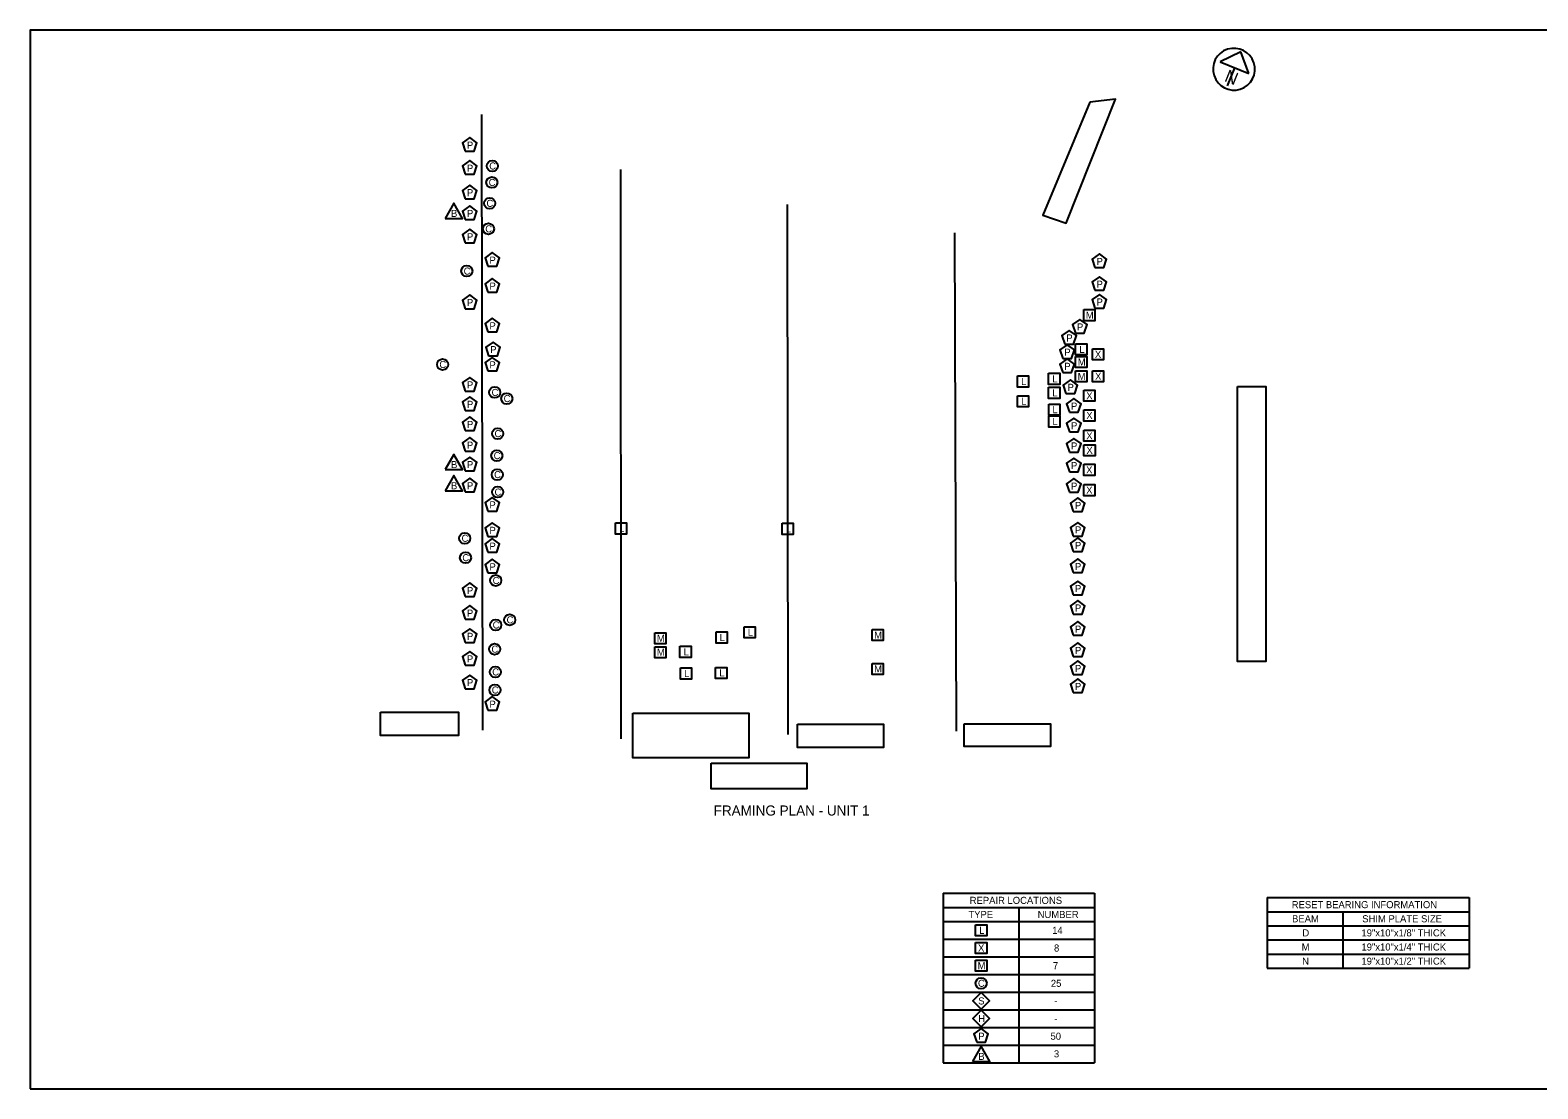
# Model space of a CAD drawing. Extents: x 100 to 161, y 98.7 to 121.
# Drawn here: x 100 to 129.89, y 100 to 121 of the extents above; entities that cross this region are included whole.
import ezdxf

# ---------------------------------------------------------------- set-up
doc = ezdxf.new("R2010")
doc.units = 0
for name, color, linetype in [('BR_P_Gen_Text', 7, 'Continuous'), ('BR_X_Sub_Centerline', 7, 'Continuous'), ('BR_X_Sub_Text', 7, 'Continuous'), ('SC_Scratch1', 7, 'Continuous'), ('SH_Data', 7, 'Continuous'), ('SH_Masking', 7, 'Continuous')]:
    doc.layers.add(name, color=color, linetype=linetype)

msp = doc.modelspace()

# ---------------------------------------------------------------- linework, layer by layer
at = {"layer": 'BR_P_Gen_Text'}
for p, q in [((118.103, 103.879), (118.103, 100.519)), ((118.103, 103.879), (121.103, 103.879)), ((121.103, 103.879), (121.103, 100.519)), ((124.527, 103.794), (124.527, 102.394)), ((124.527, 103.794), (128.527, 103.794)), ((128.527, 103.794), (128.527, 102.394)), ((118.103, 103.599), (121.103, 103.599)), ((119.603, 103.599), (119.603, 100.519)), ((124.527, 103.514), (128.527, 103.514)), ((126.027, 103.514), (126.027, 102.394)), ((118.103, 103.319), (121.103, 103.319)), ((124.527, 103.234), (128.527, 103.234)), ((118.103, 102.969), (121.103, 102.969)), ((124.527, 102.954), (128.527, 102.954)), ((118.103, 102.619), (121.103, 102.619)), ((124.527, 102.674), (128.527, 102.674)), ((118.103, 102.269), (121.103, 102.269)), ((124.527, 102.394), (128.527, 102.394)), ((118.103, 101.919), (121.103, 101.919)), ((118.103, 101.569), (121.103, 101.569)), ((118.103, 101.219), (121.103, 101.219)), ((118.103, 100.869), (121.103, 100.869)), ((118.103, 100.519), (121.103, 100.519))]:
    msp.add_line(p, q, dxfattribs=at)
for points in [[(108.627, 118.598), (108.803, 118.598), (108.858, 118.765), (108.715, 118.869), (108.573, 118.765)], [(108.627, 118.14), (108.803, 118.14), (108.858, 118.308), (108.715, 118.412), (108.573, 118.308)], [(108.627, 117.654), (108.803, 117.654), (108.858, 117.822), (108.715, 117.926), (108.573, 117.822)], [(108.225, 117.265), (108.572, 117.265), (108.398, 117.565)], [(108.627, 117.244), (108.803, 117.244), (108.858, 117.412), (108.715, 117.515), (108.573, 117.412)], [(108.627, 116.781), (108.803, 116.781), (108.858, 116.949), (108.715, 117.052), (108.573, 116.949)], [(109.074, 116.317), (109.25, 116.317), (109.304, 116.485), (109.162, 116.588), (109.019, 116.485)], [(121.109, 116.291), (121.285, 116.291), (121.34, 116.458), (121.197, 116.562), (121.054, 116.458)], [(109.074, 115.802), (109.25, 115.802), (109.304, 115.97), (109.162, 116.074), (109.019, 115.97)], [(121.109, 115.839), (121.285, 115.839), (121.34, 116.006), (121.197, 116.11), (121.054, 116.006)], [(108.627, 115.475), (108.803, 115.475), (108.858, 115.643), (108.715, 115.747), (108.573, 115.643)], [(121.109, 115.487), (121.285, 115.487), (121.34, 115.655), (121.197, 115.758), (121.054, 115.655)], [(120.886, 115.456), (121.106, 115.456), (121.106, 115.236), (120.886, 115.236)], [(109.074, 115.013), (109.25, 115.013), (109.304, 115.181), (109.162, 115.285), (109.019, 115.181)], [(120.721, 114.991), (120.897, 114.991), (120.952, 115.159), (120.809, 115.263), (120.667, 115.159)], [(109.088, 114.541), (109.265, 114.541), (109.319, 114.709), (109.177, 114.813), (109.034, 114.709)], [(120.511, 114.773), (120.687, 114.773), (120.741, 114.94), (120.599, 115.044), (120.456, 114.94)], [(109.074, 114.239), (109.25, 114.239), (109.304, 114.407), (109.162, 114.51), (109.019, 114.407)], [(120.47, 114.49), (120.646, 114.49), (120.701, 114.657), (120.558, 114.761), (120.415, 114.657)], [(120.47, 114.209), (120.646, 114.209), (120.701, 114.377), (120.558, 114.481), (120.415, 114.377)], [(120.727, 114.777), (120.947, 114.777), (120.947, 114.557), (120.727, 114.557)], [(120.727, 114.527), (120.947, 114.527), (120.947, 114.307), (120.727, 114.307)], [(121.059, 114.679), (121.279, 114.679), (121.279, 114.459), (121.059, 114.459)], [(120.191, 114.194), (120.411, 114.194), (120.411, 113.974), (120.191, 113.974)], [(120.727, 114.242), (120.947, 114.242), (120.947, 114.022), (120.727, 114.022)], [(121.062, 114.244), (121.282, 114.244), (121.282, 114.024), (121.062, 114.024)], [(108.627, 113.841), (108.803, 113.841), (108.858, 114.009), (108.715, 114.113), (108.573, 114.009)], [(119.573, 114.14), (119.793, 114.14), (119.793, 113.92), (119.573, 113.92)], [(120.191, 113.915), (120.411, 113.915), (120.411, 113.695), (120.191, 113.695)], [(120.534, 113.794), (120.71, 113.794), (120.765, 113.961), (120.622, 114.065), (120.48, 113.961)], [(108.627, 113.457), (108.803, 113.457), (108.858, 113.625), (108.715, 113.728), (108.573, 113.625)], [(119.573, 113.749), (119.793, 113.749), (119.793, 113.529), (119.573, 113.529)], [(120.603, 113.422), (120.779, 113.422), (120.834, 113.59), (120.691, 113.693), (120.548, 113.59)], [(120.888, 113.858), (121.108, 113.858), (121.108, 113.638), (120.888, 113.638)], [(108.627, 113.059), (108.803, 113.059), (108.858, 113.226), (108.715, 113.33), (108.573, 113.226)], [(120.195, 113.582), (120.415, 113.582), (120.415, 113.362), (120.195, 113.362)], [(120.195, 113.347), (120.415, 113.347), (120.415, 113.127), (120.195, 113.127)], [(120.603, 113.033), (120.779, 113.033), (120.834, 113.201), (120.691, 113.304), (120.548, 113.201)], [(120.888, 113.467), (121.108, 113.467), (121.108, 113.247), (120.888, 113.247)], [(120.888, 113.064), (121.108, 113.064), (121.108, 112.844), (120.888, 112.844)], [(108.627, 112.647), (108.803, 112.647), (108.858, 112.814), (108.715, 112.918), (108.573, 112.814)], [(120.603, 112.63), (120.779, 112.63), (120.834, 112.798), (120.691, 112.902), (120.548, 112.798)], [(120.892, 112.775), (121.112, 112.775), (121.112, 112.555), (120.892, 112.555)], [(108.225, 112.282), (108.572, 112.282), (108.398, 112.582)], [(108.627, 112.26), (108.803, 112.26), (108.858, 112.428), (108.715, 112.532), (108.573, 112.428)], [(120.603, 112.241), (120.779, 112.241), (120.834, 112.409), (120.691, 112.513), (120.548, 112.409)], [(120.886, 112.388), (121.106, 112.388), (121.106, 112.168), (120.886, 112.168)], [(108.225, 111.863), (108.572, 111.863), (108.398, 112.163)], [(108.627, 111.842), (108.803, 111.842), (108.858, 112.009), (108.715, 112.113), (108.573, 112.009)], [(120.603, 111.834), (120.779, 111.834), (120.834, 112.002), (120.691, 112.105), (120.548, 112.002)], [(120.886, 111.985), (121.106, 111.985), (121.106, 111.765), (120.886, 111.765)], [(109.074, 111.462), (109.25, 111.462), (109.304, 111.629), (109.162, 111.733), (109.019, 111.629)], [(120.681, 111.451), (120.857, 111.451), (120.911, 111.619), (120.769, 111.723), (120.626, 111.619)], [(109.074, 110.957), (109.25, 110.957), (109.304, 111.125), (109.162, 111.228), (109.019, 111.125)], [(111.605, 111.224), (111.825, 111.224), (111.825, 111.004), (111.605, 111.004)], [(114.909, 111.219), (115.129, 111.219), (115.129, 110.999), (114.909, 110.999)], [(120.681, 110.965), (120.857, 110.965), (120.911, 111.133), (120.769, 111.237), (120.626, 111.133)], [(109.074, 110.643), (109.25, 110.643), (109.304, 110.811), (109.162, 110.915), (109.019, 110.811)], [(120.681, 110.657), (120.857, 110.657), (120.911, 110.825), (120.769, 110.929), (120.626, 110.825)], [(109.074, 110.235), (109.25, 110.235), (109.304, 110.402), (109.162, 110.506), (109.019, 110.402)], [(120.681, 110.239), (120.857, 110.239), (120.911, 110.407), (120.769, 110.51), (120.626, 110.407)], [(108.627, 109.763), (108.803, 109.763), (108.858, 109.931), (108.715, 110.034), (108.573, 109.931)], [(120.681, 109.802), (120.857, 109.802), (120.911, 109.969), (120.769, 110.073), (120.626, 109.969)], [(108.627, 109.314), (108.803, 109.314), (108.858, 109.482), (108.715, 109.586), (108.573, 109.482)], [(120.681, 109.417), (120.857, 109.417), (120.911, 109.584), (120.769, 109.688), (120.626, 109.584)], [(108.627, 108.855), (108.803, 108.855), (108.858, 109.023), (108.715, 109.126), (108.573, 109.023)], [(114.155, 109.167), (114.375, 109.167), (114.375, 108.947), (114.155, 108.947)], [(116.691, 109.111), (116.911, 109.111), (116.911, 108.891), (116.691, 108.891)], [(120.681, 108.998), (120.857, 108.998), (120.911, 109.166), (120.769, 109.269), (120.626, 109.166)], [(112.383, 109.046), (112.603, 109.046), (112.603, 108.826), (112.383, 108.826)], [(113.597, 109.062), (113.817, 109.062), (113.817, 108.842), (113.597, 108.842)], [(120.681, 108.576), (120.857, 108.576), (120.911, 108.743), (120.769, 108.847), (120.626, 108.743)], [(108.627, 108.407), (108.803, 108.407), (108.858, 108.575), (108.715, 108.678), (108.573, 108.575)], [(112.383, 108.771), (112.603, 108.771), (112.603, 108.551), (112.383, 108.551)], [(112.883, 108.778), (113.103, 108.778), (113.103, 108.558), (112.883, 108.558)], [(108.627, 107.936), (108.803, 107.936), (108.858, 108.104), (108.715, 108.208), (108.573, 108.104)], [(112.893, 108.349), (113.113, 108.349), (113.113, 108.129), (112.893, 108.129)], [(113.59, 108.361), (113.81, 108.361), (113.81, 108.141), (113.59, 108.141)], [(116.691, 108.44), (116.911, 108.44), (116.911, 108.22), (116.691, 108.22)], [(120.681, 108.216), (120.857, 108.216), (120.911, 108.384), (120.769, 108.488), (120.626, 108.384)], [(120.681, 107.861), (120.857, 107.861), (120.911, 108.028), (120.769, 108.132), (120.626, 108.028)], [(109.074, 107.509), (109.25, 107.509), (109.304, 107.676), (109.162, 107.78), (109.019, 107.676)], [(118.743, 103.254), (118.963, 103.254), (118.963, 103.034), (118.743, 103.034)], [(118.743, 102.904), (118.963, 102.904), (118.963, 102.684), (118.743, 102.684)], [(118.743, 102.554), (118.963, 102.554), (118.963, 102.334), (118.743, 102.334)], [(118.853, 101.909), (119.018, 101.744), (118.853, 101.579), (118.688, 101.744)], [(118.853, 101.559), (119.018, 101.394), (118.853, 101.229), (118.688, 101.394)], [(118.765, 100.923), (118.941, 100.923), (118.995, 101.091), (118.853, 101.194), (118.71, 101.091)], [(118.679, 100.544), (119.026, 100.544), (118.853, 100.844)]]:
    msp.add_lwpolyline(points, close=True, dxfattribs=at)
for centre in [(109.164, 118.306), (109.153, 117.979), (109.109, 117.565), (109.086, 117.058), (108.657, 116.221), (108.176, 114.368), (109.211, 113.814), (109.45, 113.692), (109.269, 112.997), (109.252, 112.56), (109.26, 112.184), (109.269, 111.837), (108.616, 110.921), (108.631, 110.536), (109.231, 110.084), (109.508, 109.303), (109.231, 109.201), (109.208, 108.722), (109.223, 108.27), (109.214, 107.912), (118.853, 102.094)]:
    msp.add_circle(centre, 0.11, dxfattribs=at)
at = {"layer": 'BR_X_Sub_Centerline'}
for p, q in [((108.977, 107.116), (108.957, 119.325)), ((111.72, 106.945), (111.708, 118.234)), ((115.025, 107.026), (115.013, 117.542)), ((118.365, 107.096), (118.334, 116.979))]:
    msp.add_line(p, q, dxfattribs=at)
at = {"layer": 'BR_X_Sub_Text'}
for points in [[(106.945, 107.469), (108.492, 107.469), (108.492, 107.006), (106.945, 107.006)], [(111.949, 107.454), (114.249, 107.454), (114.249, 106.564), (111.949, 106.564)], [(115.211, 107.237), (116.917, 107.237), (116.917, 106.774), (115.211, 106.774)], [(118.514, 107.241), (120.226, 107.241), (120.226, 106.789), (118.514, 106.789)]]:
    msp.add_lwpolyline(points, close=True, dxfattribs=at)
at = {"layer": 'SC_Scratch1'}
msp.add_lwpolyline([(100, 100), (130.5, 100), (130.5, 121), (100, 121)], close=True, dxfattribs=at)
at = {"layer": 'SH_Data'}
for p, q in [((124.005, 120.571), (123.592, 120.37)), ((124.162, 120.14), (124.005, 120.571)), ((123.592, 120.37), (124.162, 120.14)), ((123.877, 120.255), (123.732, 119.896))]:
    msp.add_line(p, q, dxfattribs=at)
msp.add_arc((123.865, 120.225), 0.415, 107.7984, 107.7819, dxfattribs=at)
at = {"layer": 'SH_Masking'}
for points in [[(121.011, 119.571), (120.077, 117.328), (120.54, 117.168), (121.518, 119.633)], [(123.934, 113.934), (124.498, 113.934), (124.498, 108.48), (123.934, 108.48)], [(113.504, 106.459), (115.399, 106.459), (115.399, 105.952), (113.504, 105.952)]]:
    msp.add_lwpolyline(points, close=True, dxfattribs=at)

# ---------------------------------------------------------------- texts
at = {"layer": 'BR_P_Gen_Text'}
for s, height, p in [('P', 0.14, (108.659, 118.649)), ('C', 0.14, (109.101, 118.236)), ('P', 0.14, (108.659, 118.192)), ('P', 0.14, (108.659, 117.706)), ('C', 0.14, (109.09, 117.909)), ('C', 0.14, (109.046, 117.495)), ('B', 0.14, (108.344, 117.295)), ('P', 0.14, (108.659, 117.295)), ('P', 0.14, (108.659, 116.832)), ('C', 0.14, (109.023, 116.988)), ('C', 0.14, (108.594, 116.151)), ('P', 0.14, (109.106, 116.368)), ('P', 0.14, (121.141, 116.342)), ('P', 0.14, (109.106, 115.854)), ('P', 0.14, (121.141, 115.89)), ('P', 0.14, (121.141, 115.538)), ('P', 0.14, (108.659, 115.527)), ('M', 0.14, (120.928, 115.276)), ('P', 0.14, (109.106, 115.065)), ('P', 0.14, (120.753, 115.043)), ('P', 0.14, (120.542, 114.824)), ('P', 0.14, (109.12, 114.593)), ('P', 0.14, (120.502, 114.541)), ('M', 0.14, (120.769, 114.347)), ('L', 0.14, (120.799, 114.597)), ('X', 0.14, (121.109, 114.499)), ('C', 0.14, (108.113, 114.298)), ('P', 0.14, (109.106, 114.29)), ('P', 0.14, (120.502, 114.261)), ('M', 0.14, (120.768, 114.062)), ('X', 0.14, (121.112, 114.064)), ('P', 0.14, (108.659, 113.893)), ('C', 0.14, (109.148, 113.744)), ('L', 0.14, (119.645, 113.96)), ('L', 0.14, (120.263, 114.014)), ('P', 0.14, (120.566, 113.845)), ('P', 0.14, (108.659, 113.508)), ('C', 0.14, (109.387, 113.622)), ('L', 0.14, (119.645, 113.569)), ('L', 0.14, (120.263, 113.735)), ('P', 0.14, (120.635, 113.473)), ('X', 0.14, (120.938, 113.678)), ('L', 0.14, (120.267, 113.402)), ('L', 0.14, (120.267, 113.167)), ('X', 0.14, (120.938, 113.287)), ('P', 0.14, (108.659, 113.11)), ('C', 0.14, (109.206, 112.927)), ('P', 0.14, (120.635, 113.084)), ('X', 0.14, (120.938, 112.884)), ('P', 0.14, (108.659, 112.698)), ('P', 0.14, (120.635, 112.682)), ('X', 0.14, (120.941, 112.595)), ('B', 0.14, (108.344, 112.312)), ('P', 0.14, (108.659, 112.312)), ('C', 0.14, (109.189, 112.49)), ('P', 0.14, (120.635, 112.293)), ('C', 0.14, (109.198, 112.114)), ('X', 0.14, (120.935, 112.208)), ('B', 0.14, (108.344, 111.893)), ('P', 0.14, (108.659, 111.893)), ('C', 0.14, (109.206, 111.767)), ('P', 0.14, (120.635, 111.885)), ('X', 0.14, (120.936, 111.805)), ('P', 0.14, (109.106, 111.513)), ('P', 0.14, (120.713, 111.503)), ('C', 0.14, (108.553, 110.851)), ('P', 0.14, (109.106, 111.008)), ('L', 0.14, (111.677, 111.044)), ('L', 0.14, (114.981, 111.039)), ('P', 0.14, (120.713, 111.017)), ('C', 0.14, (108.568, 110.466)), ('P', 0.14, (109.106, 110.695)), ('P', 0.14, (120.713, 110.709)), ('P', 0.14, (109.106, 110.286)), ('P', 0.14, (120.713, 110.29)), ('C', 0.14, (109.169, 110.014)), ('P', 0.14, (108.659, 109.814)), ('P', 0.14, (120.713, 109.853)), ('P', 0.14, (108.659, 109.366)), ('P', 0.14, (120.713, 109.468)), ('C', 0.14, (109.169, 109.131)), ('C', 0.14, (109.445, 109.233)), ('L', 0.14, (114.227, 108.987)), ('P', 0.14, (120.713, 109.049)), ('P', 0.14, (108.659, 108.906)), ('M', 0.14, (112.425, 108.866)), ('L', 0.14, (113.669, 108.882)), ('M', 0.14, (116.732, 108.931)), ('P', 0.14, (108.659, 108.458)), ('C', 0.14, (109.145, 108.652)), ('M', 0.14, (112.425, 108.591)), ('L', 0.14, (112.955, 108.598)), ('P', 0.14, (120.713, 108.627)), ('C', 0.14, (109.16, 108.2)), ('L', 0.14, (112.965, 108.169)), ('L', 0.14, (113.662, 108.181)), ('M', 0.14, (116.732, 108.26)), ('P', 0.14, (120.713, 108.268)), ('P', 0.14, (108.659, 107.988)), ('C', 0.14, (109.151, 107.842)), ('P', 0.14, (120.713, 107.912)), ('P', 0.14, (109.106, 107.56)), ('FRAMING PLAN - UNIT 1', 0.2, (113.551, 105.421)), ('REPAIR LOCATIONS', 0.14, (118.627, 103.669)), ('RESET BEARING INFORMATION', 0.14, (125.011, 103.584)), ('TYPE', 0.14, (118.601, 103.389)), ('NUMBER', 0.14, (119.974, 103.389)), ('BEAM', 0.14, (125.018, 103.304)), ('SHIM PLATE SIZE', 0.14, (126.409, 103.304)), ('L', 0.14, (118.815, 103.074)), ('14', 0.14, (120.261, 103.074)), ('D', 0.14, (125.222, 103.024)), ('19"x10"x1/8" THICK', 0.14, (126.393, 103.024)), ('X', 0.14, (118.792, 102.724)), ('8', 0.14, (120.298, 102.724)), ('M', 0.14, (125.208, 102.744)), ('19"x10"x1/4" THICK', 0.14, (126.393, 102.744)), ('N', 0.14, (125.217, 102.464)), ('19"x10"x1/2" THICK', 0.14, (126.393, 102.464)), ('M', 0.14, (118.784, 102.374)), ('7', 0.14, (120.277, 102.374)), ('C', 0.14, (118.79, 102.024)), ('25', 0.14, (120.236, 102.024)), ('S', 0.14, (118.795, 101.674)), ('-', 0.14, (120.3, 101.674)), ('H', 0.14, (118.796, 101.324)), ('-', 0.14, (120.3, 101.324)), ('P', 0.14, (118.796, 100.974)), ('50', 0.14, (120.229, 100.974)), ('3', 0.14, (120.296, 100.624)), ('B', 0.14, (118.798, 100.574))]:
    msp.add_text(s, height=height, dxfattribs=at).set_placement(p)
at = {"layer": 'SH_Data'}
msp.add_text('N', height=0.25, rotation=338.0186, dxfattribs=at).set_placement((123.66, 119.993))

doc.saveas('drawing.dxf')
